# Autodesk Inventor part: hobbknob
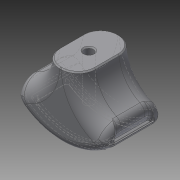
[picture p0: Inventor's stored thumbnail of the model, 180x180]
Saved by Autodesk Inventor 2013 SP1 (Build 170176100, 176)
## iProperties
Created: 2012-11
Part Number: hobbknob
Material: Generic
Document SubType Name: Modeling
Designer: Brent J. Rosenburgh
Density: 1 g/cm^3
Author: Brent J. Rosenburgh
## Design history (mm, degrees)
sketch "Sketch1"
  geometry: L1 (0, 0)-(-40, 0); L2 (-40, 0)-(-40, 30); L3 (-40, 30)-(0, 30); L4 (0, 30)-(0, 0); A1 r 30 centre (-20, 30) between (-40, 7.639) and (-20, 0); A2 r 30 centre (-20, 30) between (-20, 0) and (0, 7.639); A3 r 16.265 centre (-44.25, 30.7) between (-40, 15) and (-28, 30); A4 r 16.25 centre (4.235, 30.688) between (-12, 30) and (0, 15)
  constraints: 8 end point, 8 point on circle, 4 centre point, 4 midpoint, 4 point on line, 2 parallel, 1 coincident, 1 horizontal, 1 perpendicular
  dimensions: "d0" = 16.25 radius of A4
extrude "Extrusion1" new body sketch "Sketch1" distance "d1" = 20; taper "d2" = 0 deg
sketch "Sketch2"
  geometry: L1 (40, -15)-(40, -7.639) reference; L2 (3.198, -7.639)-(3.198, -8.839); L3 (37, -8.839)-(38, -8.239); L4 (38, -8.239)-(40, -10); L5 (37, -7.639)-(38, -7.039); L6 (38, -7.039)-(40, -8.8); L7 (12, -30)-(28, -30) reference; L8 (3.198, -7.639)-(3.198, -5.147); L9 (37, -7.639)-(37, -5.282); A1 r 27.311 centre (20.099, -29.092) between (37, -7.639) and (3.198, -7.639); A2 r 26.379 centre (20.099, -29.092) between (37, -8.839) and (3.198, -8.839); A3 r 30 centre (20, -30) between (40, -7.639) and (0, -7.639) reference; 1 further point
  constraints: 14 end point, 6 point on circle, 4 parallel, 2 centre point, 2 point on line, 1 concentric, 1 perpendicular
  dimensions: "d3" = 1.2 distance of L2.start L2.end
extrude "Extrusion2" cut sketch "Sketch2" distance "d4" = 18; taper "d5" = 0 deg
sketch "Sketch3"
  geometry: L1 (38, -7.039)-(40, -8.8) reference; L2 (40, -8.8)-(40, -7.639) reference; L3 (0, -7.639)-(0, -15) reference; L4 (12, -30)-(28, -30) reference; L5 (40, -15)-(40, -10) reference; L6 (40, -10)-(38, -8.239) reference; L7 (38, -8.239)-(37, -8.839) reference; L8 (3.198, -8.839)-(3.198, -5.147) reference; L9 (37, -7.639)-(38, -7.039) reference; L10 (40, -8.8)-(40, -10); A1 r 30 centre (20, -30) between (40, -7.639) and (0, -7.639) reference; A2 r 16.25 centre (-4.235, -30.688) between (12, -30) and (0, -15) reference; A3 r 16.265 centre (44.25, -30.7) between (40, -15) and (28, -30) reference; A4 r 26.379 centre (20.099, -29.092) between (37, -8.839) and (3.198, -8.839) reference; A5 r 27.311 centre (20.099, -29.092) between (37, -7.639) and (3.198, -7.639) reference; 1 further point
  constraints: 2 end point, 1 collinear
extrude "Extrusion3" join sketch "Sketch3" distance "d6" = 2; taper "d7" = 0 deg
sketch "Sketch4"
  geometry: L1 (37, -5.282)-(37, -7.639) reference; L2 (3.198, -8.839)-(3.198, -5.147) reference; A1 r 30 centre (20, -30) between (37, -5.282) and (3.198, -5.147) reference; A2 r 26.379 centre (20.099, -29.092) between (37, -8.839) and (3.198, -8.839) reference; A3 r 27.311 centre (20.099, -29.092) between (37, -7.639) and (3.198, -7.639); 1 further point
  constraints: 2 point on circle, 1 centre point, 1 concentric, 1 point on line
extrude "Extrusion4" join sketch "Sketch4" distance "d8" = 2; taper "d9" = 0 deg
sketch "Sketch5"
  geometry: L1 (3.198, 8.839)-(3.198, 5.147) reference; L2 (37, 5.282)-(37, 7.639) reference; A1 r 30 centre (20, 30) between (3.198, 5.147) and (37, 5.282) reference; A2 r 26.379 centre (20.099, 29.092) between (3.198, 8.839) and (37, 8.839) reference; A3 r 27.311 centre (20.099, 29.092) between (3.198, 7.639) and (37, 7.639); 1 further point
  constraints: 2 point on circle, 1 centre point, 1 concentric, 1 point on line
extrude "Extrusion5" join sketch "Sketch5" distance "d10" = 2; taper "d11" = 0 deg
sketch "Sketch6"
  geometry: L1 (40, -15)-(40, -7.639) reference; L2 (0, -7.639)-(0, -15) reference; L3 (12, -30)-(28, -30) reference; A1 r 30 centre (20, -30) between (40, -7.639) and (0, -7.639) reference; A2 r 16.25 centre (-4.235, -30.688) between (12, -30) and (0, -15) reference; A3 r 16.265 centre (44.25, -30.7) between (40, -15) and (28, -30) reference; 1 further point
extrude "Extrusion6" join sketch "Sketch6" distance "d12" = 2; taper "d13" = 0 deg
sketch "Sketch7"
  geometry: L1 (40, 15)-(40, 7.639) reference; L2 (12, 30)-(28, 30) reference; L3 (0, 7.639)-(0, 15) reference; A1 r 30 centre (20, 30) between (0, 7.639) and (40, 7.639) reference; A2 r 16.265 centre (44.25, 30.7) between (28, 30) and (40, 15) reference; A3 r 16.25 centre (-4.235, 30.688) between (0, 15) and (12, 30) reference; 1 further point
extrude "Extrusion7" join sketch "Sketch7" distance "d14" = 2; taper "d15" = 0 deg
fillet "Fillet1" dims "d16" = 18.5
fillet "Fillet2" dims "d17" = 7.75
fillet "Fillet3" dims "d18" = 3.75
chamfer "Chamfer1" distance "d19" = 0.5; stored, may be unused: second distance "d20" = 2, angle "d21" = 45 deg
fillet "Fillet4" dims "d22" = 1.75
fillet "Fillet5" dims "d23" = 1
chamfer "Chamfer2" distance "d24" = 0.5; stored, may be unused: second distance "d25" = 2, angle "d26" = 45 deg
sketch "Sketch8"
  geometry: C1 r 2 at (-8.245, 5.25); 1 further point
  constraints: 1 centre point
  dimensions: "d27" = 4 diameter of C1
extrude "Extrusion8" cut sketch "Sketch8" distance "d28" = 20; taper "d29" = 0 deg
chamfer "Chamfer3" distance "d30" = 0.5; stored, may be unused: second distance "d31" = 2, angle "d32" = 45 deg
body "Solid1"
